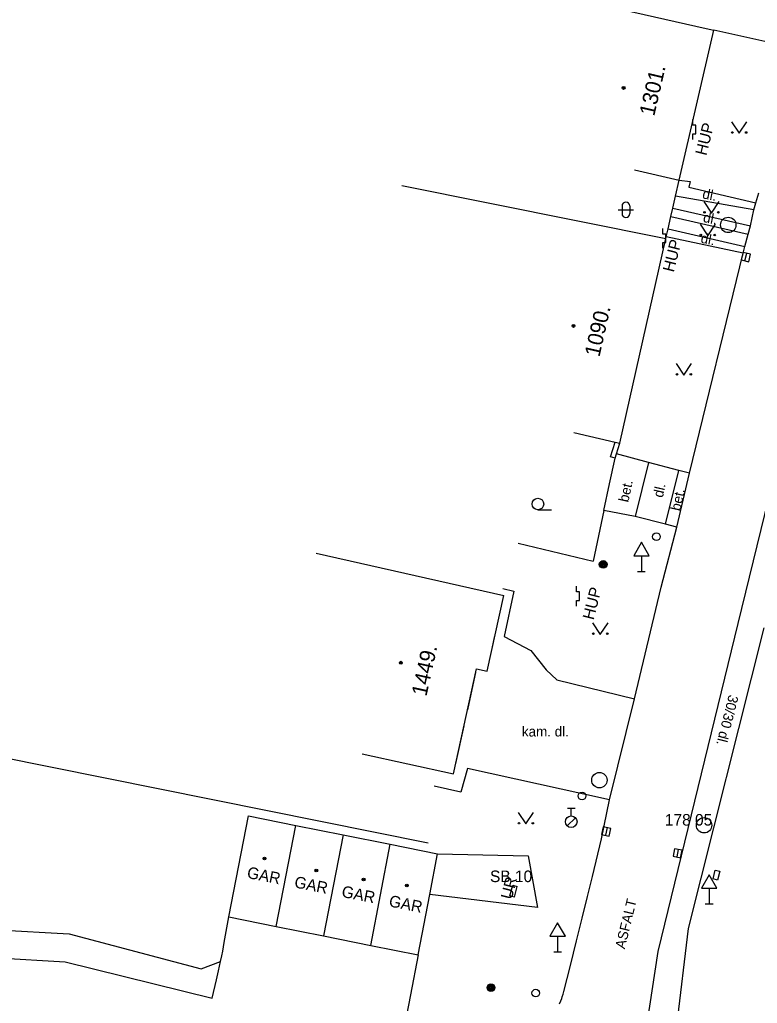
# Model space of a CAD drawing. Extents: x -540235 to -537963, y -1184915 to -1183660.
# Drawn here: x -538238.6 to -538190.8, y -1183908.6 to -1183844.8 of the extents above; entities that cross this region are included whole.
import ezdxf

# ---------------------------------------------------------------- set-up
doc = ezdxf.new("R2010")
doc.units = 0
for name, color, linetype in [('Vrstva 10', 7, 'Continuous'), ('Vrstva 11', 7, 'Continuous'), ('Vrstva 21', 7, 'Continuous'), ('Vrstva 24', 7, 'Continuous'), ('Vrstva 25', 7, 'Continuous'), ('Vrstva 27', 7, 'Continuous'), ('Vrstva 28', 7, 'Continuous'), ('Vrstva 34', 7, 'Continuous'), ('Vrstva 36', 7, 'Continuous'), ('Vrstva 39', 7, 'Continuous'), ('Vrstva 4', 7, 'Continuous'), ('Vrstva 40', 7, 'Continuous'), ('Vrstva 41', 7, 'Continuous'), ('Vrstva 47', 7, 'Continuous'), ('Vrstva 5', 7, 'Continuous'), ('Vrstva 6', 7, 'Continuous'), ('Vrstva 7', 7, 'Continuous'), ('Vrstva 8', 7, 'Continuous')]:
    doc.layers.add(name, color=color, linetype=linetype)

msp = doc.modelspace()

# ---------------------------------------------------------------- linework, layer by layer
at = {"layer": 'Vrstva 10'}
for p, q in [((-538185.57, -1183857.17), (-538192.11, -1183883.96)), ((-538191.29, -1183858.17), (-538191.06, -1183857.14)), ((-538191.43, -1183858.7), (-538191.29, -1183858.17)), ((-538191.64, -1183859.51), (-538191.43, -1183858.7)), ((-538195.23, -1183874.2), (-538191.75, -1183859.95)), ((-538191.75, -1183859.95), (-538191.64, -1183859.51)), ((-538196.05, -1183877.7), (-538195.23, -1183874.2)), ((-538197.07, -1183881.6), (-538196.05, -1183877.7)), ((-538198.79, -1183888.84), (-538197.07, -1183881.6)), ((-538192.11, -1183883.96), (-538197.28, -1183905.22)), ((-538200.41, -1183895.38), (-538198.79, -1183888.84)), ((-538200.943, -1183897.901), (-538200.41, -1183895.38)), ((-538255.61, -1183904.7), (-538235.7, -1183905.88)), ((-538197.28, -1183905.22), (-538198.06, -1183910.26)), ((-538235.7, -1183905.88), (-538226.18, -1183908.25)), ((-538203.38, -1183907.8), (-538202.951, -1183906.113))]:
    msp.add_line(p, q, dxfattribs=at)
for points in [[(-538191.06, -1183857.14), (-538190.94, -1183856.67), (-538190.74, -1183856.02)], [(-538202.951, -1183906.113), (-538202.554, -1183904.53), (-538202.188, -1183903.046), (-538201.847, -1183901.654), (-538201.531, -1183900.349), (-538200.943, -1183897.901)], [(-538226.18, -1183908.25), (-538225.893, -1183907.057), (-538225.752, -1183906.459), (-538225.684, -1183906.16), (-538225.62, -1183905.86), (-538225.547, -1183905.5), (-538225.486, -1183905.185), (-538225.384, -1183904.632), (-538225.09, -1183902.97)], [(-538212.83, -1183905.43), (-538213.325, -1183908.015), (-538213.82, -1183910.6)], [(-538203.651, -1183908.616), (-538203.573, -1183908.417), (-538203.519, -1183908.266), (-538203.481, -1183908.151), (-538203.428, -1183907.977), (-538203.38, -1183907.8)]]:
    msp.add_lwpolyline(points, dxfattribs=at)
at = {"layer": 'Vrstva 11'}
for p, q in [((-538188.5, -1183846.62), (-538193.66, -1183845.49)), ((-538191.06, -1183857.14), (-538196.15, -1183856.25)), ((-538196.442, -1183857.554), (-538191.43, -1183858.7)), ((-538196.32, -1183857.02), (-538191.29, -1183858.17)), ((-538196.628, -1183858.368), (-538191.64, -1183859.51)), ((-538191.75, -1183859.95), (-538196.743, -1183858.87)), ((-538197.9, -1183873.51), (-538199.972, -1183872.952)), ((-538197.9, -1183873.51), (-538198.76, -1183877.01)), ((-538195.93, -1183874.03), (-538197.9, -1183873.51)), ((-538196.8, -1183877.5), (-538195.93, -1183874.03)), ((-538195.23, -1183874.2), (-538195.93, -1183874.03)), ((-538198.76, -1183877.01), (-538200.78, -1183876.63)), ((-538196.8, -1183877.5), (-538198.76, -1183877.01)), ((-538196.05, -1183877.7), (-538196.8, -1183877.5)), ((-538195.29, -1183903.73), (-538190.4, -1183884.22)), ((-538203.84, -1183887.61), (-538198.79, -1183888.84)), ((-538200.41, -1183895.38), (-538209.62, -1183893.36)), ((-538255.503, -1183902.89), (-538235.44, -1183904.08)), ((-538235.44, -1183904.08), (-538226.88, -1183906.34)), ((-538196.286, -1183911.917), (-538195.29, -1183903.73)), ((-538226.88, -1183906.34), (-538225.62, -1183905.86))]:
    msp.add_line(p, q, dxfattribs=at)
for points in [[(-538195.91, -1183855.21), (-538195.2, -1183855.3), (-538195.27, -1183855.65), (-538190.94, -1183856.67)], [(-538207.33, -1183881.68), (-538206.63, -1183881.85), (-538207.24, -1183884.8), (-538205.51, -1183885.71), (-538204.53, -1183886.96), (-538203.84, -1183887.61)], [(-538209.62, -1183893.36), (-538210.06, -1183894.88), (-538211.79, -1183894.49)]]:
    msp.add_lwpolyline(points, dxfattribs=at)
at = {"layer": 'Vrstva 21'}
for p, q in [((-538211.56, -1183898.88), (-538205.68, -1183899.01)), ((-538205.68, -1183899.01), (-538205.09, -1183902.37)), ((-538205.09, -1183902.37), (-538212.074, -1183901.529))]:
    msp.add_line(p, q, dxfattribs=at)
at = {"layer": 'Vrstva 24'}
for p, q in [((-538195.009, -1183851.649), (-538195.01, -1183851.281)), ((-538194.826, -1183851.65), (-538195.009, -1183851.649)), ((-538194.826, -1183852.202), (-538194.826, -1183851.65)), ((-538195.01, -1183852.57), (-538195.009, -1183852.202)), ((-538195.009, -1183852.202), (-538194.826, -1183852.202)), ((-538196.959, -1183858.699), (-538196.96, -1183858.331)), ((-538196.776, -1183858.7), (-538196.959, -1183858.699)), ((-538196.776, -1183859.252), (-538196.776, -1183858.7)), ((-538196.96, -1183859.62), (-538196.959, -1183859.252)), ((-538196.959, -1183859.252), (-538196.776, -1183859.252)), ((-538202.549, -1183881.899), (-538202.55, -1183881.531)), ((-538202.366, -1183881.9), (-538202.549, -1183881.899)), ((-538202.366, -1183882.452), (-538202.366, -1183881.9)), ((-538202.55, -1183882.82), (-538202.549, -1183882.452)), ((-538202.549, -1183882.452), (-538202.366, -1183882.452)), ((-538193.71, -1183900.51), (-538193.569, -1183899.937)), ((-538193.569, -1183899.937), (-538193.27, -1183900.01)), ((-538193.27, -1183900.01), (-538193.41, -1183900.58)), ((-538206.87, -1183901.615), (-538206.69, -1183900.915)), ((-538206.69, -1183900.915), (-538206.4, -1183900.99)), ((-538193.41, -1183900.58), (-538193.71, -1183900.51)), ((-538206.58, -1183901.69), (-538206.4, -1183900.99)), ((-538206.58, -1183901.69), (-538206.87, -1183901.615))]:
    msp.add_line(p, q, dxfattribs=at)
at = {"layer": 'Vrstva 25'}
for centre, radius in [((-538200.83, -1183880.12), 0.25), ((-538200.83, -1183880.12), 0.2), ((-538200.83, -1183880.12), 0.15), ((-538200.83, -1183880.12), 0.1), ((-538200.83, -1183880.12), 0.05), ((-538208.1, -1183907.56), 0.25), ((-538208.1, -1183907.56), 0.2), ((-538208.1, -1183907.56), 0.15), ((-538208.1, -1183907.56), 0.1), ((-538208.1, -1183907.56), 0.05)]:
    msp.add_circle(centre, radius, dxfattribs=at)
at = {"layer": 'Vrstva 27'}
for p, q in [((-538191.642, -1183860.432), (-538191.518, -1183859.948)), ((-538200.577, -1183897.186), (-538200.683, -1183897.674)), ((-538195.964, -1183898.594), (-538196.056, -1183899.086))]:
    msp.add_line(p, q, dxfattribs=at)
for points in [[(-538191.399, -1183860.494), (-538191.276, -1183860.009), (-538191.761, -1183859.886), (-538191.884, -1183860.371)], [(-538200.821, -1183897.132), (-538200.928, -1183897.621), (-538200.439, -1183897.728), (-538200.332, -1183897.239)], [(-538196.209, -1183898.548), (-538196.302, -1183899.039), (-538195.811, -1183899.132), (-538195.718, -1183898.641)]]:
    msp.add_lwpolyline(points, close=True, dxfattribs=at)
for centre in [(-538192.722, -1183858.109), (-538201.072, -1183894.104), (-538194.29, -1183897.03)]:
    msp.add_circle(centre, 0.5, dxfattribs=at)
at = {"layer": 'Vrstva 28'}
for p, q in [((-538203.15, -1183895.925), (-538202.65, -1183895.925)), ((-538202.9, -1183896.425), (-538202.9, -1183895.925)), ((-538203.158, -1183897.072), (-538202.628, -1183896.542))]:
    msp.add_line(p, q, dxfattribs=at)
for centre, radius in [((-538197.38, -1183878.32), 0.25), ((-538202.2, -1183895.13), 0.25), ((-538202.9, -1183896.8), 0.375), ((-538205.2, -1183907.91), 0.25)]:
    msp.add_circle(centre, radius, dxfattribs=at)
at = {"layer": 'Vrstva 34'}
for p, q in [((-538198.35, -1183879.552), (-538198.35, -1183880.57)), ((-538198.6, -1183880.57), (-538198.1, -1183880.57)), ((-538193.96, -1183901.112), (-538193.96, -1183902.13)), ((-538194.21, -1183902.13), (-538193.71, -1183902.13)), ((-538203.78, -1183904.222), (-538203.78, -1183905.24)), ((-538204.03, -1183905.24), (-538203.53, -1183905.24))]:
    msp.add_line(p, q, dxfattribs=at)
for points in [[(-538198.85, -1183879.552), (-538197.85, -1183879.552), (-538198.35, -1183878.686)], [(-538194.46, -1183901.112), (-538193.46, -1183901.112), (-538193.96, -1183900.246)], [(-538204.28, -1183904.222), (-538203.28, -1183904.222), (-538203.78, -1183903.356)]]:
    msp.add_lwpolyline(points, close=True, dxfattribs=at)
at = {"layer": 'Vrstva 36'}
for p, q in [((-538199.608, -1183856.878), (-538199.608, -1183857.378)), ((-538199.108, -1183856.878), (-538199.108, -1183857.378)), ((-538199.858, -1183857.128), (-538198.858, -1183857.128)), ((-538205.059, -1183876.577), (-538204.184, -1183876.577))]:
    msp.add_line(p, q, dxfattribs=at)
for points in [[(-538192.511, -1183851.419), (-538192.011, -1183852.169), (-538191.511, -1183851.419)], [(-538194.313, -1183856.586), (-538193.813, -1183857.336), (-538193.313, -1183856.586)], [(-538194.548, -1183858.068), (-538194.048, -1183858.818), (-538193.548, -1183858.068)], [(-538196.1, -1183867.101), (-538195.6, -1183867.851), (-538195.1, -1183867.101)], [(-538201.515, -1183883.91), (-538201.015, -1183884.66), (-538200.515, -1183883.91)], [(-538206.34, -1183896.198), (-538205.84, -1183896.948), (-538205.34, -1183896.198)]]:
    msp.add_lwpolyline(points, dxfattribs=at)
for centre, radius in [((-538192.4612, -1183852.1188), 0.05), ((-538191.5618, -1183852.1188), 0.05), ((-538194.2632, -1183857.2858), 0.05), ((-538193.3638, -1183857.2858), 0.05), ((-538194.4982, -1183858.7678), 0.05), ((-538193.5988, -1183858.7678), 0.05), ((-538196.0502, -1183867.8008), 0.05), ((-538195.1508, -1183867.8008), 0.05), ((-538205.0591, -1183876.2019), 0.375), ((-538201.4652, -1183884.6098), 0.05), ((-538200.5658, -1183884.6098), 0.05), ((-538206.2902, -1183896.8978), 0.05), ((-538205.3908, -1183896.8978), 0.05)]:
    msp.add_circle(centre, radius, dxfattribs=at)
for centre, start, end in [((-538199.3577, -1183856.8783), 0, 180), ((-538199.3577, -1183857.3783), 180, 0)]:
    msp.add_arc(centre, 0.25, start, end, dxfattribs=at)
at = {"layer": 'Vrstva 39'}
for centre, radius in [((-538199.505, -1183849.229), 0.09), ((-538199.505, -1183849.229), 0.0398), ((-538202.756, -1183864.659), 0.09), ((-538202.756, -1183864.659), 0.0398), ((-538213.95, -1183886.491), 0.09), ((-538213.95, -1183886.491), 0.0398), ((-538222.781, -1183899.179), 0.09), ((-538222.781, -1183899.179), 0.0398), ((-538219.42, -1183899.962), 0.09), ((-538219.42, -1183899.962), 0.0398), ((-538216.353, -1183900.55), 0.09), ((-538216.353, -1183900.55), 0.0398), ((-538213.547, -1183900.942), 0.09), ((-538213.547, -1183900.942), 0.0398)]:
    msp.add_circle(centre, radius, dxfattribs=at)
at = {"layer": 'Vrstva 5'}
for p, q in [((-538203.24, -1183843.31), (-538194.147, -1183845.377)), ((-538194.147, -1183845.377), (-538193.66, -1183845.49)), ((-538195.91, -1183855.21), (-538193.66, -1183845.49)), ((-538198.8, -1183854.54), (-538195.91, -1183855.21)), ((-538213.88, -1183855.55), (-538196.77, -1183858.99)), ((-538199.76, -1183872.25), (-538196.77, -1183858.99)), ((-538202.73, -1183871.57), (-538200.053, -1183872.184)), ((-538200.053, -1183872.184), (-538199.76, -1183872.25)), ((-538219.42, -1183879.4), (-538207.27, -1183882.13)), ((-538208.35, -1183887.04), (-538207.27, -1183882.13)), ((-538210.53, -1183893.7), (-538209.04, -1183886.89)), ((-538209.04, -1183886.89), (-538208.35, -1183887.04)), ((-538216.44, -1183892.4), (-538210.53, -1183893.7)), ((-538225.09, -1183902.97), (-538223.82, -1183896.42)), ((-538223.82, -1183896.42), (-538220.755, -1183897.035)), ((-538222.025, -1183903.585), (-538220.755, -1183897.035)), ((-538220.755, -1183897.035), (-538217.69, -1183897.65)), ((-538217.69, -1183897.65), (-538218.96, -1183904.2)), ((-538217.69, -1183897.65), (-538214.625, -1183898.265)), ((-538215.895, -1183904.815), (-538214.625, -1183898.265)), ((-538214.625, -1183898.265), (-538211.56, -1183898.88)), ((-538225.09, -1183902.97), (-538222.025, -1183903.585)), ((-538222.025, -1183903.585), (-538218.96, -1183904.2)), ((-538218.96, -1183904.2), (-538215.895, -1183904.815)), ((-538215.895, -1183904.815), (-538212.83, -1183905.43))]:
    msp.add_line(p, q, dxfattribs=at)
msp.add_lwpolyline([(-538212.83, -1183905.43), (-538212.074, -1183901.529), (-538211.56, -1183898.88)], dxfattribs=at)
at = {"layer": 'Vrstva 6'}
for p, q in [((-538208.02, -1183885.56), (-538207.85, -1183884.75)), ((-538209.61, -1183889.55), (-538209.09, -1183887.12)), ((-538210.37, -1183893.03), (-538209.84, -1183890.58))]:
    msp.add_line(p, q, dxfattribs=at)
at = {"layer": 'Vrstva 7'}
for p, q in [((-538200.347, -1183873.153), (-538200.053, -1183872.184)), ((-538200.06, -1183873.24), (-538200.347, -1183873.153)), ((-538200.78, -1183876.63), (-538201.47, -1183879.9)), ((-538206.333, -1183878.737), (-538201.47, -1183879.9)), ((-538251.53, -1183890.24), (-538212.179, -1183898.167))]:
    msp.add_line(p, q, dxfattribs=at)
msp.add_lwpolyline([(-538200.06, -1183873.24), (-538199.972, -1183872.952), (-538199.76, -1183872.25)], dxfattribs=at)
at = {"layer": 'Vrstva 8'}
for points in [[(-538196.77, -1183858.99), (-538196.743, -1183858.87), (-538196.628, -1183858.368), (-538196.442, -1183857.554), (-538196.32, -1183857.02), (-538196.15, -1183856.25), (-538195.91, -1183855.21)], [(-538200.78, -1183876.63), (-538200.413, -1183874.902), (-538200.06, -1183873.24)]]:
    msp.add_lwpolyline(points, dxfattribs=at)

# ---------------------------------------------------------------- texts
at = {"layer": 'Vrstva 4'}
msp.add_text('178 05 ', height=0.75, dxfattribs=at).set_placement((-538196.83, -1183897.05))
at = {"layer": 'Vrstva 40'}
for s, rotation, p in [('dl.', 348.613908, (-538194.439, -1183856.381)), ('dl.', 348.613908, (-538194.394, -1183857.912)), ('dl.', 348.613908, (-538194.548, -1183859.259)), ('bet.', 77.272472, (-538199.212, -1183876.128)), ('dl.', 77.272472, (-538196.974, -1183875.827)), ('bet.', 77.272472, (-538195.842, -1183876.693)), ('30/30 dl.', 255.726011, (-538192.682, -1183888.538)), ('ASFALT', 76.256097, (-538199.431, -1183905.085))]:
    msp.add_text(s, height=0.65, rotation=rotation, dxfattribs=at).set_placement(p)
msp.add_text('kam. dl.', height=0.65, dxfattribs=at).set_placement((-538206.097, -1183891.275))
at = {"layer": 'Vrstva 41'}
for s, rotation, p in [('HUP', 75.985808, (-538194.145, -1183853.654)), ('HUP', 75.985808, (-538196.258, -1183861.215)), ('HUP', 75.985808, (-538201.447, -1183883.757)), ('GAR', 348.654122, (-538223.953, -1183900.436)), ('GAR', 348.654122, (-538220.887, -1183901.051)), ('UR', 75.579222, (-538206.759, -1183901.883)), ('GAR', 348.654122, (-538217.823, -1183901.666)), ('GAR', 348.654122, (-538214.757, -1183902.281))]:
    msp.add_text(s, height=0.75, rotation=rotation, dxfattribs=at).set_placement(p)
msp.add_text('SB 10', height=0.75, dxfattribs=at).set_placement((-538208.162, -1183900.715))
at = {"layer": 'Vrstva 47'}
for s, rotation, p in [('1301.', 76.966644, (-538197.525, -1183851.101)), ('1090.', 77.292886, (-538201.074, -1183866.71)), ('1449.', 77.599458, (-538212.288, -1183888.717))]:
    msp.add_text(s, height=1, rotation=rotation, dxfattribs=at).set_placement(p)

doc.saveas('drawing.dxf')
